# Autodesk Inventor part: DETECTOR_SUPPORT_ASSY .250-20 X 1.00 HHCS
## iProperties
Shininess: 64.0
Length Units: 11272
Angle Units: 11279
Time Units: 11290
Mass Units: 11286
Length Display Precision: 3
Angle Display Precision: 2
Compacted: True
Part Number: DETECTOR_SUPPORT_ASSY .250-20 X 1.00 HHCS
Document SubType Name: Modeling
Created: 2004-08
Designer: John Blackburn
Material: STAINLESS_STEEL, AUSTENITIC
Manufacturer: Standard
Standards Organization: Custom
Density: 0.0
Volumn: 0.0
Area: 0.0
PropertySet Name: Model Information
Control State: 0
Master: False
Checked Out: False
Author: John Blackburn
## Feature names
1. Base1
2. ExtrusionBlind1
3. Chamfer1
